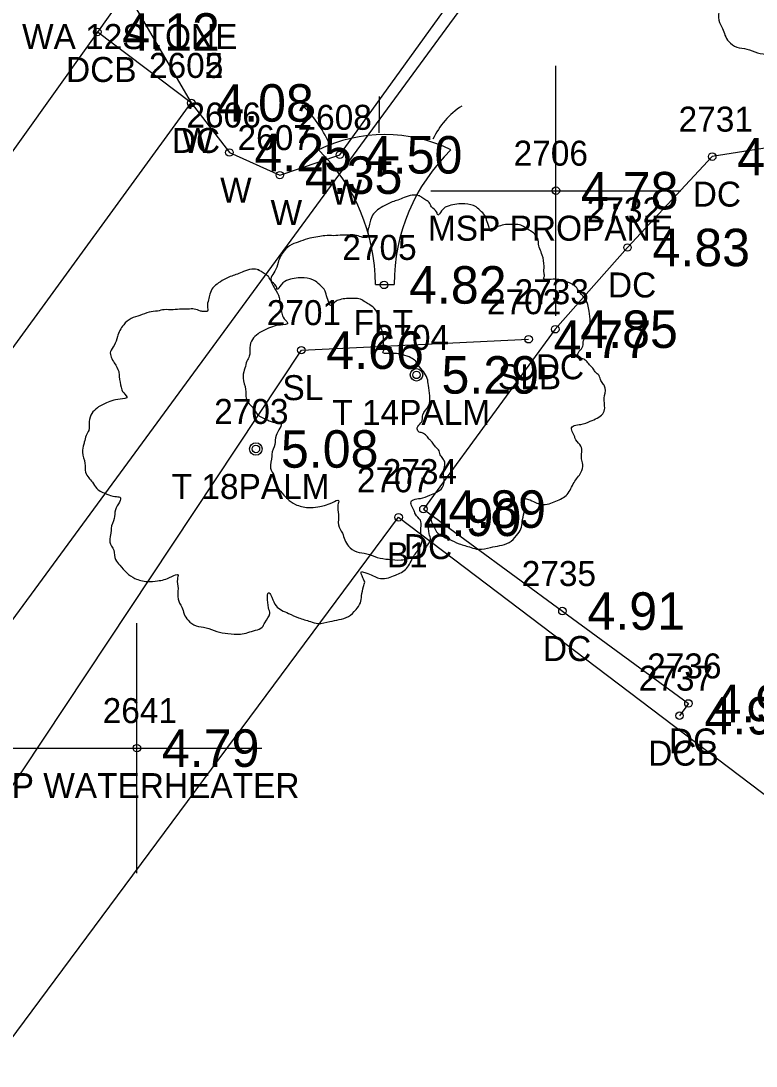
# Model space of a CAD drawing. Extents: x 2608598 to 2610682, y 641451 to 643526.
# Drawn here: x 2610106.78 to 2610136.19, y 641996.54 to 642038.34 of the extents above; entities that cross this region are included whole.
import ezdxf

# ---------------------------------------------------------------- set-up
doc = ezdxf.new("R2010")
doc.units = 0
for name, color, linetype in [('RD_EX_Bldg', 7, 'Continuous'), ('RD_EX_Bldg_txCode', 7, 'Continuous'), ('RD_EX_BldgApp', 7, 'Continuous'), ('RD_EX_BldgApp_txCode', 7, 'Continuous'), ('RD_EX_Conc', 7, 'Continuous'), ('RD_EX_Conc_txCode', 7, 'Continuous'), ('RD_EX_Fence_Other', 7, 'Continuous'), ('RD_EX_Misc', 7, 'Continuous'), ('RD_EX_Misc_txCode', 7, 'Continuous'), ('RD_EX_TX_Bldg_ELEV', 7, 'Continuous'), ('RD_EX_TX_BldgApp_ELEV', 7, 'Continuous'), ('RD_EX_TX_Conc_ELEV', 7, 'Continuous'), ('RD_EX_TX_Misc_ELEV', 7, 'Continuous'), ('RD_EX_TX_VEG_ELEV', 7, 'Continuous'), ('RD_EX_VEG', 7, 'Continuous'), ('RD_EX_VEG_txCode', 7, 'Continuous'), ('RD_SMD_Locator', 7, 'Continuous')]:
    doc.layers.add(name, color=color, linetype=linetype)

msp = doc.modelspace()

# ---------------------------------------------------------------- linework, layer by layer
at = {"layer": 'RD_EX_Bldg'}
for points in [[(2610053.59, 642011.651), (2610094.327, 642068.736), (2610111.856, 642055.619), (2610105.498, 642045.99), (2610112.03, 642040.97), (2610078.047, 641993.35), (2610053.59, 642011.651)], [(2610074.75, 641955.019), (2610121.892, 642018.487), (2610144.774, 642001.166), (2610097.632, 641937.698), (2610074.75, 641955.019)]]:
    msp.add_lwpolyline(points, dxfattribs=at)
at = {"layer": 'RD_EX_BldgApp'}
msp.add_line((2610120.961, 642027.8), (2610121.711, 642027.8), dxfattribs=at)
msp.add_lwpolyline([(2610111.175, 642039.216), (2610113.596, 642035.061), (2610115.12, 642033.077), (2610117.139, 642032.173), (2610119.539, 642032.985), (2610125.556, 642041.329)], dxfattribs=at)
for centre, radius, start, end in [((2610083.255, 642035.138), 37.876, 358.0671, 0.2715), ((2610114.644, 642031.443), 4.895, 24.3279, 46.2665), ((2610126.225, 642032.193), 3.283, 123.2906, 154.4886), ((2610121.336, 642027.8), 5.997, 63.7794, 116.2206), ((2610113.461, 642027.8), 7.5, 0, 45.8366), ((2610129.211, 642027.8), 7.5, 134.1634, 180)]:
    msp.add_arc(centre, radius, start, end, dxfattribs=at)
at = {"layer": 'RD_EX_Conc'}
for points in [[(2610160.612, 642047.272), (2610156.554, 642041.695), (2610152.931, 642037.213), (2610150.731, 642035.233), (2610148.01, 642033.912), (2610141.177, 642033.459), (2610141.177, 642033.459), (2610137.988, 642033.476), (2610134.44, 642032.913), (2610131.048, 642029.279), (2610128.16, 642026.009), (2610122.885, 642018.814), (2610128.446, 642014.737), (2610133.488, 642011.041), (2610133.129, 642010.552)], [(2610092.106, 642013.051), (2610095.692, 642010.492), (2610113.596, 642035.061), (2610109.837, 642037.898)]]:
    msp.add_lwpolyline(points, dxfattribs=at)
at = {"layer": 'RD_EX_Fence_Other'}
msp.add_lwpolyline([(2610147.084, 642069.782), (2610125.734, 642040.697), (2610098.694, 642003.858), (2610084.195, 641984.008), (2610080.523, 641986.54)], dxfattribs=at)
at = {"layer": 'RD_EX_Misc'}
for p, q in [((2610128.186, 642026.551), (2610128.186, 642036.551)), ((2610123.186, 642031.551), (2610133.186, 642031.551)), ((2610111.421, 642004.254), (2610111.421, 642014.254)), ((2610106.421, 642009.254), (2610116.421, 642009.254))]:
    msp.add_line(p, q, dxfattribs=at)
at = {"layer": 'RD_EX_VEG'}
msp.add_lwpolyline([(2610084.48, 641974.656), (2610118, 642025.172), (2610127.094, 642025.609)], dxfattribs=at)
for centre, radius in [((2610122.607, 642024.183), 0.25), ((2610122.594, 642024.164), 0.0001), ((2610116.182, 642021.22), 0.25), ((2610116.169, 642021.201), 0.0001)]:
    msp.add_circle(centre, radius, dxfattribs=at)
for points in [[(2610137.949, 642051.536), (2610137.649, 642051.561), (2610137.324, 642051.461), (2610137.074, 642051.361), (2610136.849, 642051.286), (2610136.624, 642051.186), (2610136.324, 642051.011), (2610136.1, 642050.811), (2610135.975, 642050.561), (2610135.925, 642050.336), (2610135.875, 642050.062), (2610135.875, 642049.887), (2610135.75, 642049.862), (2610135.6, 642049.887), (2610135.35, 642049.962), (2610135.1, 642049.962), (2610134.85, 642049.962), (2610134.5, 642049.937), (2610134.15, 642049.937), (2610133.876, 642049.887), (2610133.551, 642049.837), (2610133.176, 642049.712), (2610132.826, 642049.587), (2610132.526, 642049.337), (2610132.276, 642048.862), (2610132.151, 642048.512), (2610132.001, 642048.262), (2610132.151, 642047.813), (2610132.326, 642047.463), (2610132.351, 642047.263), (2610132.426, 642046.838), (2610132.526, 642046.613), (2610132.651, 642046.413), (2610132.576, 642046.388), (2610132.201, 642046.338), (2610131.901, 642046.238), (2610131.477, 642046.013), (2610131.252, 642045.788), (2610131.152, 642045.464), (2610131.127, 642045.114), (2610131.027, 642044.914), (2610130.952, 642044.639), (2610130.927, 642044.564), (2610130.877, 642044.239), (2610130.977, 642043.789), (2610131.002, 642043.439), (2610131.127, 642043.215), (2610131.277, 642043.04), (2610131.452, 642042.79), (2610131.851, 642042.565), (2610132.176, 642042.465), (2610132.376, 642042.44), (2610132.201, 642041.94), (2610132.151, 642041.59), (2610132.026, 642041.19), (2610132.026, 642041.116), (2610131.976, 642040.641), (2610132.126, 642040.316), (2610132.201, 642039.941), (2610132.376, 642039.716), (2610132.651, 642039.416), (2610132.976, 642039.191), (2610133.476, 642039.066), (2610133.876, 642039.091), (2610134.45, 642039.266), (2610134.7, 642039.341), (2610134.675, 642039.166), (2610134.7, 642038.791), (2610134.7, 642038.367), (2610134.85, 642038.042), (2610134.95, 642037.767), (2610135.1, 642037.517), (2610135.425, 642037.292), (2610135.825, 642037.217), (2610136.249, 642037.067), (2610136.699, 642036.992), (2610137.199, 642036.967), (2610137.799, 642037.117), (2610138.074, 642037.242), (2610138.174, 642037.417), (2610138.374, 642037.792), (2610138.324, 642038.017), (2610138.349, 642038.617), (2610138.448, 642038.442), (2610138.623, 642038.092), (2610139.123, 642037.792), (2610139.523, 642037.617), (2610139.998, 642037.467), (2610140.298, 642037.392), (2610140.772, 642037.467), (2610141.147, 642037.542), (2610141.522, 642037.667), (2610141.822, 642037.942), (2610141.997, 642038.217), (2610142.047, 642038.492), (2610142.122, 642038.866), (2610142.172, 642039.041)], [(2610122.739, 642031.35), (2610122.439, 642031.375), (2610122.114, 642031.275), (2610121.864, 642031.175), (2610121.639, 642031.1), (2610121.415, 642031), (2610121.115, 642030.825), (2610120.89, 642030.625), (2610120.765, 642030.375), (2610120.715, 642030.15), (2610120.665, 642029.876), (2610120.665, 642029.701), (2610120.54, 642029.676), (2610120.39, 642029.701), (2610120.14, 642029.776), (2610119.89, 642029.776), (2610119.64, 642029.776), (2610119.29, 642029.751), (2610118.941, 642029.751), (2610118.666, 642029.701), (2610118.341, 642029.651), (2610117.966, 642029.526), (2610117.616, 642029.401), (2610117.316, 642029.151), (2610117.066, 642028.676), (2610116.941, 642028.326), (2610116.792, 642028.076), (2610116.941, 642027.627), (2610117.116, 642027.277), (2610117.141, 642027.077), (2610117.216, 642026.652), (2610117.316, 642026.427), (2610117.441, 642026.227), (2610117.366, 642026.202), (2610116.991, 642026.152), (2610116.692, 642026.052), (2610116.267, 642025.827), (2610116.042, 642025.602), (2610115.942, 642025.277), (2610115.917, 642024.928), (2610115.817, 642024.728), (2610115.742, 642024.453), (2610115.717, 642024.378), (2610115.667, 642024.053), (2610115.767, 642023.603), (2610115.792, 642023.253), (2610115.917, 642023.028), (2610116.067, 642022.854), (2610116.242, 642022.604), (2610116.642, 642022.379), (2610116.966, 642022.279), (2610117.166, 642022.254), (2610116.991, 642021.754), (2610116.941, 642021.404), (2610116.817, 642021.004), (2610116.817, 642020.929), (2610116.767, 642020.455), (2610116.916, 642020.13), (2610116.991, 642019.755), (2610117.166, 642019.53), (2610117.441, 642019.23), (2610117.766, 642019.005), (2610118.266, 642018.88), (2610118.666, 642018.905), (2610119.241, 642019.08), (2610119.49, 642019.155), (2610119.465, 642018.98), (2610119.49, 642018.605), (2610119.49, 642018.181), (2610119.64, 642017.856), (2610119.74, 642017.581), (2610119.89, 642017.331), (2610120.215, 642017.106), (2610120.615, 642017.031), (2610121.04, 642016.881), (2610121.49, 642016.806), (2610121.989, 642016.781), (2610122.589, 642016.931), (2610122.864, 642017.056), (2610122.964, 642017.231), (2610123.164, 642017.606), (2610123.114, 642017.831), (2610123.139, 642018.431), (2610123.239, 642018.256), (2610123.414, 642017.906), (2610123.913, 642017.606), (2610124.313, 642017.431), (2610124.788, 642017.281), (2610125.088, 642017.206), (2610125.563, 642017.281), (2610125.938, 642017.356), (2610126.312, 642017.481), (2610126.612, 642017.756), (2610126.787, 642018.031), (2610126.837, 642018.306), (2610126.912, 642018.68), (2610126.962, 642018.855)], [(2610126.962, 642018.855), (2610126.887, 642019.03), (2610126.837, 642019.28), (2610126.912, 642019.255), (2610127.087, 642019.205), (2610127.362, 642019.08), (2610127.587, 642019.005), (2610127.912, 642019.03), (2610128.187, 642019.13), (2610128.636, 642019.405), (2610128.911, 642019.88), (2610129.186, 642020.28), (2610129.261, 642020.605), (2610129.211, 642020.829), (2610129.186, 642021.329), (2610128.986, 642021.579), (2610128.936, 642021.704), (2610128.836, 642022.104), (2610128.911, 642022.154), (2610129.186, 642022.204), (2610129.561, 642022.329), (2610129.836, 642022.454), (2610130.061, 642022.629), (2610130.136, 642022.854), (2610130.111, 642023.253), (2610130.161, 642023.653), (2610130.086, 642023.803), (2610129.986, 642023.953), (2610129.911, 642024.153), (2610129.761, 642024.303), (2610129.661, 642024.453), (2610129.561, 642024.553), (2610129.436, 642024.703), (2610129.261, 642024.828), (2610129.111, 642024.878), (2610129.061, 642025.028), (2610129.211, 642025.228), (2610129.261, 642025.327), (2610129.286, 642025.552), (2610129.511, 642025.902), (2610129.561, 642026.302), (2610129.511, 642026.727), (2610129.461, 642027.002), (2610129.311, 642027.277), (2610129.111, 642027.527), (2610128.986, 642027.701), (2610128.811, 642027.826), (2610128.486, 642027.951), (2610128.237, 642028.001), (2610127.887, 642028.001), (2610127.687, 642028.051), (2610127.712, 642028.101), (2610127.712, 642028.251), (2610127.712, 642028.526), (2610127.637, 642028.976), (2610127.487, 642029.476), (2610127.487, 642029.501), (2610127.387, 642029.751), (2610127.162, 642029.95), (2610126.987, 642030.05), (2610126.787, 642030.175), (2610126.537, 642030.2), (2610126.237, 642030.2), (2610125.963, 642030.15), (2610125.763, 642030.05), (2610125.588, 642029.925), (2610125.513, 642030.075), (2610125.413, 642030.375), (2610125.363, 642030.525), (2610125.213, 642030.7), (2610124.988, 642030.9), (2610124.538, 642031.025), (2610123.913, 642030.95), (2610123.614, 642030.75), (2610123.464, 642030.575), (2610123.414, 642030.7), (2610123.214, 642030.9), (2610123.114, 642031.075), (2610122.939, 642031.2), (2610122.789, 642031.3), (2610122.689, 642031.35)], [(2610116.314, 642028.387), (2610116.014, 642028.412), (2610115.689, 642028.312), (2610115.439, 642028.212), (2610115.214, 642028.137), (2610114.989, 642028.037), (2610114.689, 642027.862), (2610114.464, 642027.662), (2610114.339, 642027.413), (2610114.289, 642027.188), (2610114.24, 642026.913), (2610114.24, 642026.738), (2610114.115, 642026.713), (2610113.965, 642026.738), (2610113.715, 642026.813), (2610113.465, 642026.813), (2610113.215, 642026.813), (2610112.865, 642026.788), (2610112.515, 642026.788), (2610112.24, 642026.738), (2610111.916, 642026.688), (2610111.541, 642026.563), (2610111.191, 642026.438), (2610110.891, 642026.188), (2610110.641, 642025.713), (2610110.516, 642025.363), (2610110.366, 642025.114), (2610110.516, 642024.664), (2610110.691, 642024.314), (2610110.716, 642024.114), (2610110.791, 642023.689), (2610110.891, 642023.464), (2610111.016, 642023.264), (2610110.941, 642023.239), (2610110.566, 642023.189), (2610110.266, 642023.089), (2610109.841, 642022.865), (2610109.617, 642022.64), (2610109.517, 642022.315), (2610109.492, 642021.965), (2610109.392, 642021.765), (2610109.317, 642021.49), (2610109.292, 642021.415), (2610109.242, 642021.09), (2610109.342, 642020.64), (2610109.367, 642020.291), (2610109.492, 642020.066), (2610109.642, 642019.891), (2610109.816, 642019.641), (2610110.216, 642019.416), (2610110.541, 642019.316), (2610110.741, 642019.291), (2610110.566, 642018.791), (2610110.516, 642018.441), (2610110.391, 642018.042), (2610110.391, 642017.967), (2610110.341, 642017.492), (2610110.491, 642017.167), (2610110.566, 642016.792), (2610110.741, 642016.567), (2610111.016, 642016.267), (2610111.341, 642016.043), (2610111.841, 642015.918), (2610112.24, 642015.943), (2610112.815, 642016.117), (2610113.065, 642016.192), (2610113.04, 642016.018), (2610113.065, 642015.643), (2610113.065, 642015.218), (2610113.215, 642014.893), (2610113.315, 642014.618), (2610113.465, 642014.368), (2610113.79, 642014.143), (2610114.19, 642014.068), (2610114.614, 642013.918), (2610115.064, 642013.843), (2610115.564, 642013.818), (2610116.164, 642013.968), (2610116.439, 642014.093), (2610116.539, 642014.268), (2610116.738, 642014.643), (2610116.688, 642014.868), (2610116.713, 642015.468), (2610116.813, 642015.293), (2610116.988, 642014.943), (2610117.488, 642014.643), (2610117.888, 642014.468), (2610118.363, 642014.318), (2610118.663, 642014.243), (2610119.137, 642014.318), (2610119.512, 642014.393), (2610119.887, 642014.518), (2610120.187, 642014.793), (2610120.362, 642015.068), (2610120.412, 642015.343), (2610120.487, 642015.718), (2610120.537, 642015.893)], [(2610120.537, 642015.893), (2610120.462, 642016.068), (2610120.412, 642016.317), (2610120.487, 642016.292), (2610120.662, 642016.242), (2610120.937, 642016.117), (2610121.162, 642016.043), (2610121.486, 642016.068), (2610121.761, 642016.167), (2610122.211, 642016.442), (2610122.486, 642016.917), (2610122.761, 642017.317), (2610122.836, 642017.642), (2610122.786, 642017.867), (2610122.761, 642018.366), (2610122.561, 642018.616), (2610122.511, 642018.741), (2610122.411, 642019.141), (2610122.486, 642019.191), (2610122.761, 642019.241), (2610123.136, 642019.366), (2610123.411, 642019.491), (2610123.635, 642019.666), (2610123.71, 642019.891), (2610123.685, 642020.291), (2610123.735, 642020.69), (2610123.66, 642020.84), (2610123.56, 642020.99), (2610123.485, 642021.19), (2610123.336, 642021.34), (2610123.236, 642021.49), (2610123.136, 642021.59), (2610123.011, 642021.74), (2610122.836, 642021.865), (2610122.686, 642021.915), (2610122.636, 642022.065), (2610122.786, 642022.265), (2610122.836, 642022.365), (2610122.861, 642022.59), (2610123.086, 642022.939), (2610123.136, 642023.339), (2610123.086, 642023.764), (2610123.036, 642024.039), (2610122.886, 642024.314), (2610122.686, 642024.564), (2610122.561, 642024.739), (2610122.386, 642024.864), (2610122.061, 642024.989), (2610121.811, 642025.039), (2610121.461, 642025.039), (2610121.261, 642025.089), (2610121.286, 642025.139), (2610121.286, 642025.288), (2610121.286, 642025.563), (2610121.211, 642026.013), (2610121.062, 642026.513), (2610121.062, 642026.538), (2610120.962, 642026.788), (2610120.737, 642026.988), (2610120.562, 642027.088), (2610120.362, 642027.213), (2610120.112, 642027.238), (2610119.812, 642027.238), (2610119.537, 642027.188), (2610119.337, 642027.088), (2610119.162, 642026.963), (2610119.087, 642027.113), (2610118.987, 642027.413), (2610118.937, 642027.562), (2610118.788, 642027.737), (2610118.563, 642027.937), (2610118.113, 642028.062), (2610117.488, 642027.987), (2610117.188, 642027.787), (2610117.038, 642027.612), (2610116.988, 642027.737), (2610116.788, 642027.937), (2610116.688, 642028.112), (2610116.514, 642028.237), (2610116.364, 642028.337), (2610116.264, 642028.387)]]:
    msp.add_spline(points, degree=3, dxfattribs=at)
at = {"layer": 'RD_SMD_Locator'}
for centre in [(2610109.837, 642037.898), (2610113.596, 642035.061), (2610113.596, 642035.061), (2610115.12, 642033.077), (2610119.539, 642032.985), (2610134.44, 642032.913), (2610117.139, 642032.173), (2610128.186, 642031.551), (2610131.048, 642029.279), (2610121.308, 642027.782), (2610128.16, 642026.009), (2610127.094, 642025.609), (2610118, 642025.172), (2610122.607, 642024.183), (2610116.182, 642021.22), (2610122.885, 642018.814), (2610121.892, 642018.487), (2610128.446, 642014.737), (2610133.488, 642011.041), (2610133.129, 642010.552), (2610111.421, 642009.254)]:
    msp.add_circle(centre, 0.15, dxfattribs=at)

# ---------------------------------------------------------------- texts
at = {"layer": 'RD_EX_Bldg_txCode'}
for s, p in [('2707', (2610120.222, 642019.487)), ('B1', (2610121.419, 642016.487))]:
    msp.add_text(s, height=1, dxfattribs=at).set_placement(p)
at = {"layer": 'RD_EX_BldgApp_txCode'}
for s, p in [('2705', (2610119.639, 642028.782)), ('FLT', (2610120.088, 642025.782))]:
    msp.add_text(s, height=1, dxfattribs=at).set_placement(p)
at = {"layer": 'RD_EX_Conc_txCode'}
for s, p in [('DCB', (2610108.585, 642035.898)), ('2602', (2610111.903, 642036.061)), ('2731', (2610133.094, 642033.913)), ('DC', (2610112.816, 642033.061)), ('DC', (2610133.661, 642030.913)), ('2732', (2610129.418, 642030.279)), ('2733', (2610126.53, 642027.009)), ('DC', (2610130.268, 642027.279)), ('DC', (2610127.38, 642024.009)), ('2734', (2610121.255, 642019.814)), ('DC', (2610122.105, 642016.814)), ('2735', (2610126.816, 642015.737)), ('DC', (2610127.667, 642012.737)), ('2736', (2610131.835, 642012.041)), ('2737', (2610131.499, 642011.552)), ('DC', (2610132.709, 642009.041)), ('DCB', (2610131.877, 642008.552))]:
    msp.add_text(s, height=1, dxfattribs=at).set_placement(p)
at = {"layer": 'RD_EX_Misc_txCode'}
for s, p in [('WA 12STONE', (2610106.825, 642037.216)), ('2605', (2610111.903, 642036.061)), ('2606', (2610113.403, 642034.077)), ('2608', (2610117.846, 642033.985)), ('W', (2610113.226, 642033.061)), ('2607', (2610115.446, 642033.173)), ('2706', (2610126.493, 642032.551)), ('W', (2610114.75, 642031.077)), ('W', (2610119.169, 642030.985)), ('W', (2610116.769, 642030.173)), ('MSP PROPANE', (2610123.064, 642029.551)), ('2641', (2610110.051, 642010.254)), ('MSP WATERHEATER', (2610104.405, 642007.254))]:
    msp.add_text(s, height=1, dxfattribs=at).set_placement(p)
at = {"layer": 'RD_EX_TX_Bldg_ELEV'}
msp.add_text('4.90', height=1.5, dxfattribs=at).set_placement((2610122.892, 642017.737))
at = {"layer": 'RD_EX_TX_BldgApp_ELEV'}
msp.add_text('4.82', height=1.5, dxfattribs=at).set_placement((2610122.308, 642027.032))
at = {"layer": 'RD_EX_TX_Conc_ELEV'}
for s, p in [('4.12', (2610110.837, 642037.148)), ('4.08', (2610114.596, 642034.311)), ('4.74', (2610135.44, 642032.163)), ('4.83', (2610132.048, 642028.529)), ('4.85', (2610129.16, 642025.259)), ('4.89', (2610123.885, 642018.064)), ('4.91', (2610129.446, 642013.987)), ('4.93', (2610134.488, 642010.291)), ('4.98', (2610134.129, 642009.802))]:
    msp.add_text(s, height=1.5, dxfattribs=at).set_placement(p)
at = {"layer": 'RD_EX_TX_Misc_ELEV'}
for s, p in [('4.08', (2610114.596, 642034.311)), ('4.25', (2610116.12, 642032.327)), ('4.50', (2610120.539, 642032.235)), ('4.35', (2610118.139, 642031.423)), ('4.78', (2610129.186, 642030.801)), ('4.79', (2610112.421, 642008.504))]:
    msp.add_text(s, height=1.5, dxfattribs=at).set_placement(p)
at = {"layer": 'RD_EX_TX_VEG_ELEV'}
for s, p in [('4.77', (2610128.094, 642024.859)), ('4.66', (2610119, 642024.422)), ('5.29', (2610123.607, 642023.433)), ('5.08', (2610117.182, 642020.47))]:
    msp.add_text(s, height=1.5, dxfattribs=at).set_placement(p)
at = {"layer": 'RD_EX_VEG_txCode'}
for s, p in [('2702', (2610125.425, 642026.609)), ('2701', (2610116.615, 642026.172)), ('2704', (2610120.938, 642025.183)), ('SLB', (2610125.865, 642023.609)), ('SL', (2610117.244, 642023.172)), ('2703', (2610114.512, 642022.22)), ('T 14PALM', (2610119.237, 642022.183)), ('T 18PALM', (2610112.812, 642019.22))]:
    msp.add_text(s, height=1, dxfattribs=at).set_placement(p)

doc.saveas('drawing.dxf')
